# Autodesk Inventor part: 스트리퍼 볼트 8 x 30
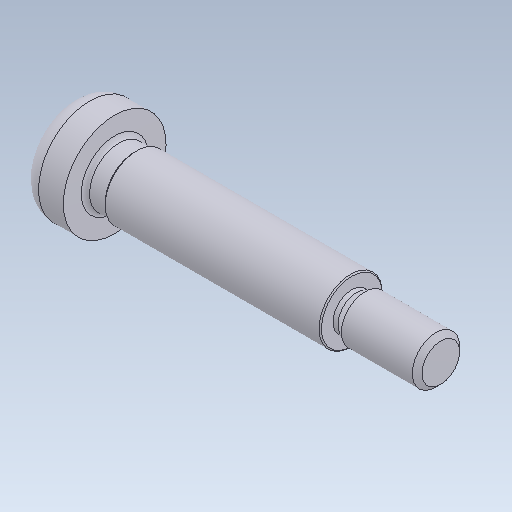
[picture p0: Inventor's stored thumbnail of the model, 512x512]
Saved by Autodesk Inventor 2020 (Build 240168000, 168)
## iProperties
Created: 2024-04
Part Number: 스트리퍼 볼트 8 x 30
Material: 강철, 연강
Description: 6각 소켓 머리 숄더 나사
Document SubType Name: Modeling
Designer: oem
Density: 7.86 g/cm^3
Appearance: 기본값
Mass: 19.0633 g
Surface Area: 14.6092 cm^2
Volume: 2.42536 cm^3
Sending System: Autodesk Inventor 2025
Preprocessor: ST-DEVELOPER v20
Author: jhkim
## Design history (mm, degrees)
feature "Solid1"
node "솔리드1"
